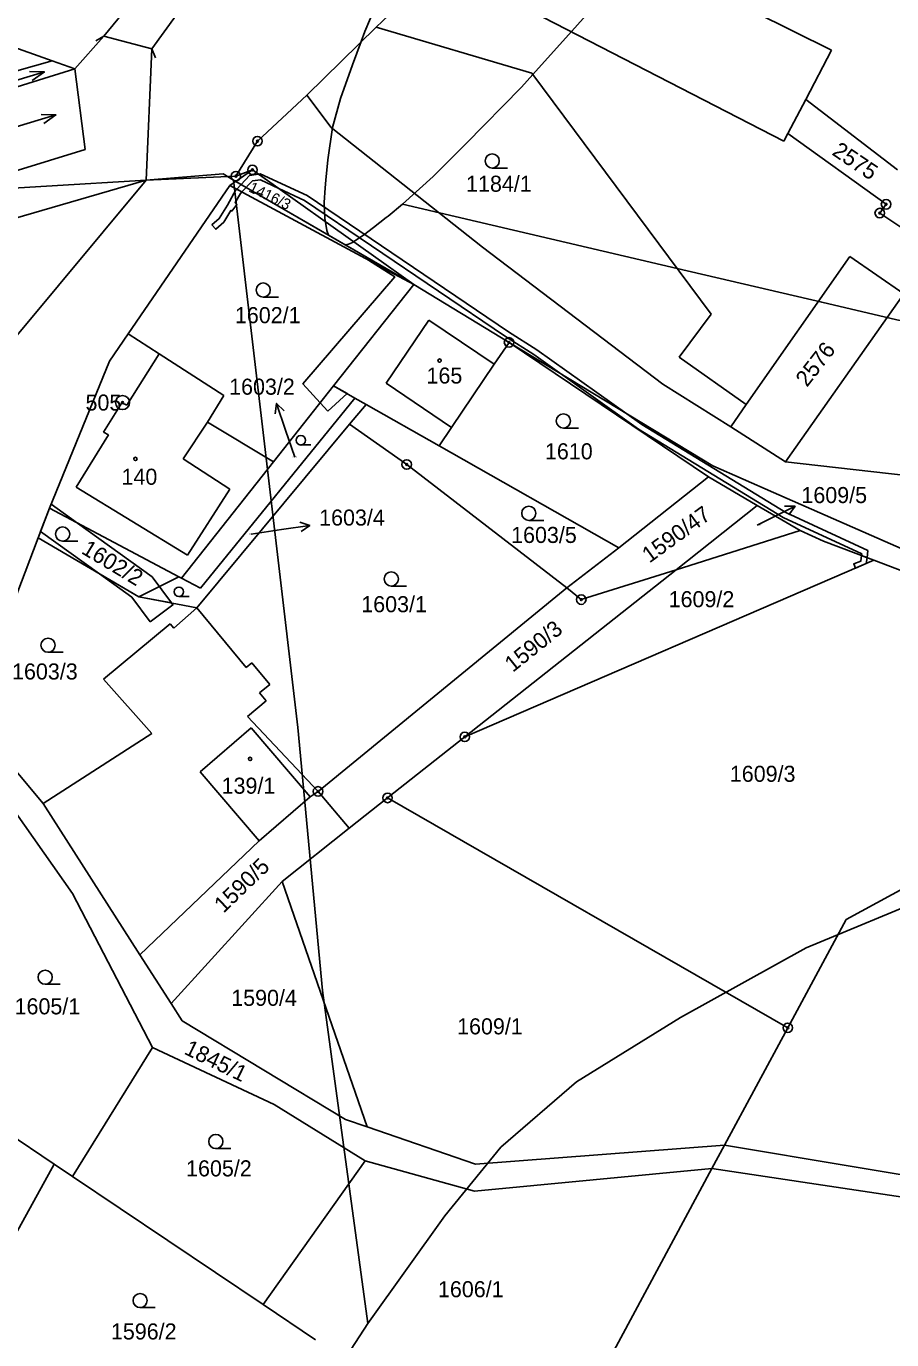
# Model space of a CAD drawing. Extents: x -546762 to -540209, y -1046851 to -1035694.
# Drawn here: x -543445.9 to -543354.2, y -1040714.9 to -1040575.9 of the extents above; entities that cross this region are included whole.
import ezdxf

# ---------------------------------------------------------------- set-up
doc = ezdxf.new("R2010")
doc.units = 0
for name, color, linetype in [('Vrstva 1', 7, 'Continuous'), ('Vrstva 13', 7, 'Continuous'), ('Vrstva 16', 7, 'Continuous'), ('Vrstva 17', 7, 'Continuous'), ('Vrstva 18', 7, 'Continuous'), ('Vrstva 19', 7, 'Continuous'), ('Vrstva 24', 7, 'Continuous'), ('Vrstva 25', 7, 'Continuous'), ('Vrstva 26', 7, 'Continuous'), ('Vrstva 3', 7, 'Continuous'), ('Vrstva 30', 7, 'Continuous'), ('Vrstva 37', 7, 'Continuous'), ('Vrstva 4', 7, 'Continuous'), ('Vrstva 52', 7, 'Continuous'), ('Vrstva 6', 7, 'Continuous')]:
    doc.layers.add(name, color=color, linetype=linetype)

msp = doc.modelspace()

# ---------------------------------------------------------------- linework, layer by layer
at = {"layer": 'Vrstva 1'}
for p, q in [((-543408.83, -1040575.99), (-543416.18, -1040583.21)), ((-543443.15, -1040579.57), (-543463, -1040585.19)), ((-543440.75, -1040580.42), (-543473.23, -1040590.44)), ((-543439.65, -1040588.95), (-543440.75, -1040580.42)), ((-543424.32, -1040592.74), (-543421.93, -1040591.11)), ((-543396.33, -1040611.67), (-543394.76, -1040609.36)), ((-543369.64, -1040615.95), (-543376.76, -1040610.94)), ((-543411.64, -1040618.01), (-543405.6, -1040622.28)), ((-543405.6, -1040622.28), (-543388.63, -1040635.35)), ((-543368.48, -1040626.62), (-543377.08, -1040633.42)), ((-543377.08, -1040633.42), (-543363.94, -1040629.27)), ((-543399.45, -1040651.12), (-543356.13, -1040632.42)), ((-543377.08, -1040633.42), (-543399.45, -1040651.12)), ((-543387.11, -1040636.59), (-543377.08, -1040633.42)), ((-543388.63, -1040635.35), (-543414.99, -1040656.88)), ((-543388.63, -1040635.35), (-543387.11, -1040636.59)), ((-543422.47, -1040648.96), (-543414.99, -1040656.88)), ((-543407.62, -1040657.58), (-543399.45, -1040651.12)), ((-543415.81, -1040657.47), (-543421.21, -1040662.11)), ((-543415.81, -1040657.47), (-543414.99, -1040656.88)), ((-543414.99, -1040656.88), (-543411.68, -1040660.79)), ((-543411.68, -1040660.79), (-543407.62, -1040657.58)), ((-543407.62, -1040657.58), (-543365.25, -1040681.9)), ((-543421.21, -1040662.11), (-543433.85, -1040674.17)), ((-543359.07, -1040670.43), (-543365.25, -1040681.9)), ((-543365.25, -1040681.9), (-543371.93, -1040694.31))]:
    msp.add_line(p, q, dxfattribs=at)
for points in [[(-543432.91, -1040571.12), (-543437.66, -1040576.95)], [(-543432.59, -1040578.31), (-543428.67, -1040572.85)], [(-543408.83, -1040575.99), (-543404.82, -1040572.14)], [(-543368.81, -1040574.39), (-543360.61, -1040578.44)], [(-543437.66, -1040576.95), (-543440.75, -1040580.42)], [(-543408.83, -1040575.99), (-543392.34, -1040580.86)], [(-543443.15, -1040579.57), (-543448.19, -1040577.78)], [(-543433.19, -1040592.18), (-543432.59, -1040578.31)], [(-543440.75, -1040580.42), (-543443.15, -1040579.57)], [(-543360.61, -1040578.44), (-543363.35, -1040583.66)], [(-543392.34, -1040580.86), (-543373.36, -1040606.36)], [(-543416.18, -1040583.21), (-543421.4, -1040588.06)], [(-543413.59, -1040586.61), (-543416.18, -1040583.21)], [(-543363.35, -1040583.66), (-543365.24, -1040587.27)], [(-543353.63, -1040591.1), (-543363.35, -1040583.66)], [(-543413.59, -1040586.61), (-543397.58, -1040599.28)], [(-543421.4, -1040588.06), (-543423.68, -1040591.77)], [(-543365.24, -1040587.27), (-543354.84, -1040594.75)], [(-543454.33, -1040593.48), (-543439.65, -1040588.95)], [(-543459.21, -1040599.73), (-543433.19, -1040592.18)], [(-543447.01, -1040608.82), (-543433.19, -1040592.18)], [(-543424.32, -1040592.74), (-543435.08, -1040608.45)], [(-543404.86, -1040603.25), (-543424.32, -1040592.74)], [(-543354.84, -1040594.75), (-543355.51, -1040595.67)], [(-543355.51, -1040595.67), (-543349.68, -1040599.58)], [(-543397.58, -1040599.28), (-543378.46, -1040613.77)], [(-543358.68, -1040600.27), (-543369.64, -1040615.95)], [(-543358.68, -1040600.27), (-543352.96, -1040604.23)], [(-543413.34, -1040613.96), (-543404.86, -1040603.25)], [(-543365.48, -1040621.99), (-543352.96, -1040604.23)], [(-543376.76, -1040610.94), (-543373.36, -1040606.36)], [(-543435.08, -1040608.45), (-543437.06, -1040611.34)], [(-543435.08, -1040608.45), (-543431.81, -1040610.56)], [(-543443.42, -1040626.92), (-543437.06, -1040611.34)], [(-543431.81, -1040610.56), (-543424.95, -1040614.97)], [(-543400.85, -1040618.37), (-543396.33, -1040611.67)], [(-543419.71, -1040622), (-543413.34, -1040613.96)], [(-543413.34, -1040613.96), (-543411.08, -1040615.25)], [(-543371.29, -1040618.31), (-543378.46, -1040613.77)], [(-543411.08, -1040615.25), (-543427.45, -1040635.37)], [(-543426.69, -1040617.8), (-543424.95, -1040614.97)], [(-543409.9, -1040615.92), (-543411.64, -1040618.01)], [(-543411.08, -1040615.25), (-543409.9, -1040615.92)], [(-543409.9, -1040615.92), (-543402.16, -1040620.31)], [(-543369.64, -1040615.95), (-543371.29, -1040618.31)], [(-543411.64, -1040618.01), (-543427.83, -1040637.44)], [(-543426.69, -1040617.8), (-543419.71, -1040622)], [(-543400.85, -1040618.37), (-543402.16, -1040620.31)], [(-543371.29, -1040618.31), (-543365.48, -1040621.99)], [(-543402.16, -1040620.31), (-543383.13, -1040631.11)], [(-543429.45, -1040634.31), (-543419.71, -1040622)], [(-543352.7, -1040623.46), (-543365.48, -1040621.99)], [(-543383.13, -1040631.11), (-543373.64, -1040623.6)], [(-543443.42, -1040626.92), (-543444.61, -1040630.05)], [(-543443.42, -1040626.92), (-543429.72, -1040634.17)], [(-543444.61, -1040630.05), (-543451.84, -1040648.94)], [(-543444.61, -1040630.05), (-543433.97, -1040636.3)], [(-543383.13, -1040631.11), (-543388.63, -1040635.35)], [(-543433.97, -1040636.3), (-543429.72, -1040634.17)], [(-543429.45, -1040634.31), (-543429.72, -1040634.17)], [(-543427.45, -1040635.37), (-543429.45, -1040634.31)], [(-543433.97, -1040636.3), (-543427.83, -1040637.44)], [(-543430.26, -1040639.61), (-543427.83, -1040637.44)], [(-543427.83, -1040637.44), (-543422.61, -1040643.77)], [(-543437.72, -1040644.99), (-543430.64, -1040639.15)], [(-543430.64, -1040639.15), (-543430.26, -1040639.61)], [(-543422.61, -1040643.77), (-543421.99, -1040643.26)], [(-543421.99, -1040643.26), (-543420.09, -1040645.57)], [(-543432.58, -1040650.76), (-543437.72, -1040644.99)], [(-543420.09, -1040645.57), (-543421.17, -1040646.46)], [(-543421.17, -1040646.46), (-543420.47, -1040647.31)], [(-543420.47, -1040647.31), (-543422.47, -1040648.96)], [(-543451.84, -1040648.94), (-543444.11, -1040658.18)], [(-543444.11, -1040658.18), (-543432.58, -1040650.76)], [(-543448.16, -1040657.49), (-543441, -1040667.68)], [(-543333.92, -1040656.78), (-543359.07, -1040670.43)], [(-543444.11, -1040658.18), (-543433.85, -1040674.17)], [(-543411.68, -1040660.79), (-543418.78, -1040666.41)], [(-543418.78, -1040666.41), (-543430.54, -1040679.33)], [(-543418.78, -1040666.41), (-543409.8, -1040692.4)], [(-543441, -1040667.68), (-543432.53, -1040683.98)], [(-543433.85, -1040674.17), (-543430.54, -1040679.33)], [(-543430.54, -1040679.33), (-543429.36, -1040681.17)], [(-543412.08, -1040691.62), (-543429.36, -1040681.17)], [(-543463.43, -1040682.52), (-543442.94, -1040696.32)], [(-543440.99, -1040697.63), (-543432.53, -1040683.98)], [(-543419.62, -1040690.03), (-543432.53, -1040683.98)], [(-543410.01, -1040695.99), (-543419.62, -1040690.03)], [(-543409.8, -1040692.4), (-543412.08, -1040691.62)], [(-543398.31, -1040696.34), (-543409.8, -1040692.4)], [(-543371.93, -1040694.31), (-543398.31, -1040696.34)], [(-543373.27, -1040696.81), (-543371.93, -1040694.31)], [(-543447.01, -1040703.78), (-543442.94, -1040696.32)], [(-543442.94, -1040696.32), (-543440.99, -1040697.63)], [(-543420.78, -1040711.2), (-543410.01, -1040695.99)], [(-543398.41, -1040699.19), (-543410.01, -1040695.99)], [(-543440.99, -1040697.63), (-543420.78, -1040711.2)], [(-543373.27, -1040696.81), (-543398.41, -1040699.19)], [(-543390.01, -1040727.91), (-543373.27, -1040696.81)], [(-543420.78, -1040711.2), (-543415.25, -1040714.92)]]:
    msp.add_lwpolyline(points, dxfattribs=at)
at = {"layer": 'Vrstva 13'}
msp.add_line((-543433.19, -1040592.18), (-543423.68, -1040591.77), dxfattribs=at)
msp.add_line((-543433.19, -1040592.18), (-543423.68, -1040591.77), dxfattribs=at)
for points in [[(-543454.33, -1040593.48), (-543433.19, -1040592.18)], [(-543454.33, -1040593.48), (-543433.19, -1040592.18)], [(-543421.93, -1040591.11), (-543423.68, -1040591.77)], [(-543421.93, -1040591.11), (-543423.68, -1040591.77)], [(-543404.86, -1040603.25), (-543421.93, -1040591.11)], [(-543404.86, -1040603.25), (-543421.93, -1040591.11)], [(-543394.76, -1040609.36), (-543404.86, -1040603.25)], [(-543394.76, -1040609.36), (-543404.86, -1040603.25)], [(-543394.76, -1040609.36), (-543373.64, -1040623.6)], [(-543394.76, -1040609.36), (-543373.64, -1040623.6)], [(-543368.48, -1040626.62), (-543373.64, -1040623.6)], [(-543368.48, -1040626.62), (-543373.64, -1040623.6)], [(-543368.48, -1040626.62), (-543363.94, -1040629.27)], [(-543368.48, -1040626.62), (-543363.94, -1040629.27)], [(-543361.47, -1040630.39), (-543363.94, -1040629.27)], [(-543361.47, -1040630.39), (-543363.94, -1040629.27)], [(-543356.13, -1040632.42), (-543361.47, -1040630.39)], [(-543356.13, -1040632.42), (-543361.47, -1040630.39)], [(-543333.49, -1040641.01), (-543356.13, -1040632.42)], [(-543333.49, -1040641.01), (-543356.13, -1040632.42)]]:
    msp.add_lwpolyline(points, dxfattribs=at)
at = {"layer": 'Vrstva 16'}
for p, q in [((-543418.42, -1040618.66), (-543419.38, -1040615.82)), ((-543367.15, -1040628.05), (-543364.47, -1040626.71)), ((-543418.84, -1040629.18), (-543415.87, -1040628.75))]:
    msp.add_line(p, q, dxfattribs=at)
for points in [[(-543419.54, -1040616.93), (-543419.38, -1040615.82), (-543418.59, -1040616.61)], [(-543417.45, -1040621.52), (-543418.42, -1040618.66)], [(-543365.58, -1040626.71), (-543364.47, -1040626.71), (-543365.14, -1040627.6)], [(-543416.93, -1040628.4), (-543415.87, -1040628.75), (-543416.79, -1040629.38)], [(-543368.47, -1040628.71), (-543367.15, -1040628.05)], [(-543422.08, -1040629.66), (-543418.84, -1040629.18)]]:
    msp.add_lwpolyline(points, dxfattribs=at)
at = {"layer": 'Vrstva 24'}
for centre, radius in [((-543421.4, -1040588.06), 0.5), ((-543421.4, -1040588.06), 0.1), ((-543421.93, -1040591.11), 0.5), ((-543423.68, -1040591.77), 0.5), ((-543423.68, -1040591.77), 0.1), ((-543421.93, -1040591.11), 0.1), ((-543354.84, -1040594.75), 0.5), ((-543354.84, -1040594.75), 0.1), ((-543355.51, -1040595.67), 0.5), ((-543355.51, -1040595.67), 0.1), ((-543394.76, -1040609.36), 0.5), ((-543394.76, -1040609.36), 0.1), ((-543435.69, -1040615.73), 0.75), ((-543435.69, -1040615.73), 0.1), ((-543405.6, -1040622.28), 0.5), ((-543405.6, -1040622.28), 0.1), ((-543387.11, -1040636.59), 0.5), ((-543387.11, -1040636.59), 0.1), ((-543399.45, -1040651.12), 0.5), ((-543399.45, -1040651.12), 0.1), ((-543414.99, -1040656.88), 0.5), ((-543414.99, -1040656.88), 0.1), ((-543407.62, -1040657.58), 0.5), ((-543407.62, -1040657.58), 0.1), ((-543365.25, -1040681.9), 0.5), ((-543365.25, -1040681.9), 0.1)]:
    msp.add_circle(centre, radius, dxfattribs=at)
at = {"layer": 'Vrstva 25'}
for p, q in [((-543396.54, -1040590.91), (-543394.94, -1040590.91)), ((-543420.79, -1040604.57), (-543419.19, -1040604.57)), ((-543389.01, -1040618.43), (-543387.41, -1040618.43)), ((-543416.81, -1040620.22), (-543415.74, -1040620.22)), ((-543392.67, -1040628.2), (-543391.07, -1040628.2)), ((-543442.03, -1040630.4), (-543440.43, -1040630.4)), ((-543407.23, -1040635.15), (-543405.63, -1040635.15)), ((-543429.72, -1040636.26), (-543428.65, -1040636.26)), ((-543443.58, -1040642.16), (-543441.98, -1040642.16)), ((-543443.88, -1040677.3), (-543442.28, -1040677.3)), ((-543425.81, -1040694.69), (-543424.21, -1040694.69)), ((-543433.83, -1040711.52), (-543432.23, -1040711.52))]:
    msp.add_line(p, q, dxfattribs=at)
for points in [[(-543449.71, -1040582.47), (-543443.97, -1040580.73), (-543445.55, -1040580.69)], [(-543443.97, -1040580.73), (-543445.26, -1040581.64)], [(-543448.48, -1040587.02), (-543442.74, -1040585.28), (-543444.32, -1040585.24)], [(-543442.74, -1040585.28), (-543444.03, -1040586.19)]]:
    msp.add_lwpolyline(points, dxfattribs=at)
for centre, radius in [((-543396.54, -1040590.16), 0.75), ((-543420.79, -1040603.82), 0.75), ((-543402.12, -1040611.29), 0.175), ((-543389.01, -1040617.68), 0.75), ((-543416.81, -1040619.72), 0.503), ((-543434.32, -1040621.7), 0.175), ((-543392.67, -1040627.45), 0.75), ((-543442.03, -1040629.65), 0.75), ((-543407.23, -1040634.4), 0.75), ((-543429.72, -1040635.76), 0.503), ((-543443.58, -1040641.41), 0.75), ((-543422.18, -1040653.44), 0.175), ((-543443.88, -1040676.55), 0.75), ((-543425.81, -1040693.94), 0.75), ((-543433.83, -1040710.77), 0.75)]:
    msp.add_circle(centre, radius, dxfattribs=at)
at = {"layer": 'Vrstva 26'}
for p, q in [((-543437.66, -1040576.95), (-543438.53, -1040577.45)), ((-543432.59, -1040578.31), (-543432.19, -1040579.23))]:
    msp.add_line(p, q, dxfattribs=at)
at = {"layer": 'Vrstva 3'}
for points in [[(-543391.11, -1040574.97), (-543365.67, -1040588.08)], [(-543368.81, -1040574.39), (-543360.61, -1040578.44)], [(-543360.61, -1040578.44), (-543363.35, -1040583.66)], [(-543363.35, -1040583.66), (-543365.24, -1040587.27)], [(-543365.24, -1040587.27), (-543365.67, -1040588.08)], [(-543403.26, -1040607), (-543407.79, -1040613.68)], [(-543396.33, -1040611.67), (-543403.26, -1040607)], [(-543431.81, -1040610.56), (-543435.24, -1040616.02)], [(-543431.81, -1040610.56), (-543424.95, -1040614.97)], [(-543400.85, -1040618.37), (-543396.33, -1040611.67)], [(-543407.79, -1040613.68), (-543400.85, -1040618.37)], [(-543435.78, -1040615.75), (-543437.69, -1040618.85)], [(-543435.24, -1040616.02), (-543435.78, -1040615.75)], [(-543426.69, -1040617.8), (-543424.95, -1040614.97)], [(-543426.69, -1040617.8), (-543429.28, -1040621.7)], [(-543437.18, -1040619.16), (-543440.59, -1040624.69)], [(-543437.69, -1040618.85), (-543437.18, -1040619.16)], [(-543429.28, -1040621.7), (-543424.32, -1040624.89)], [(-543428.8, -1040631.87), (-543440.59, -1040624.69)], [(-543424.32, -1040624.89), (-543428.8, -1040631.87)], [(-543427.48, -1040654.8), (-543422.08, -1040650.16)], [(-543422.08, -1040650.16), (-543415.81, -1040657.47)], [(-543421.21, -1040662.11), (-543427.48, -1040654.8)], [(-543415.81, -1040657.47), (-543421.21, -1040662.11)]]:
    msp.add_lwpolyline(points, dxfattribs=at)
at = {"layer": 'Vrstva 30'}
for p, q in [((-543421.3, -1040591.56), (-543421.1, -1040591.53)), ((-543419.15, -1040593.09), (-543421.3, -1040591.56)), ((-543421.1, -1040591.53), (-543416.13, -1040593.82)), ((-543416.43, -1040594.34), (-543419.15, -1040593.09)), ((-543395.14, -1040608.74), (-543416.43, -1040594.34)), ((-543416.13, -1040593.82), (-543394.82, -1040608.24)), ((-543392.15, -1040610.65), (-543395.14, -1040608.74)), ((-543394.82, -1040608.24), (-543391.81, -1040610.15)), ((-543391.81, -1040610.15), (-543380.7, -1040618.05)), ((-543381.04, -1040618.55), (-543392.15, -1040610.65)), ((-543365.72, -1040627.91), (-543381.04, -1040618.55)), ((-543380.7, -1040618.05), (-543365.44, -1040627.37)), ((-543357.41, -1040631.74), (-543365.72, -1040627.91)), ((-543365.44, -1040627.37), (-543356.75, -1040631.38)), ((-543357.43, -1040631.93), (-543357.41, -1040631.74)), ((-543356.85, -1040632.15), (-543357.43, -1040631.93)), ((-543356.75, -1040631.38), (-543356.85, -1040632.15))]:
    msp.add_line(p, q, dxfattribs=at)
for points in [[(-543421.94, -1040592.27), (-543423.05, -1040593.43), (-543423.6, -1040593.13), (-543422.24, -1040591.71), (-543421.3, -1040591.56), (-543419.15, -1040593.09), (-543421.09, -1040592.14), (-543421.94, -1040592.27)], [(-543423.6, -1040593.13), (-543423.05, -1040593.43), (-543423.21, -1040593.59), (-543423.75, -1040594.57), (-543423.59, -1040594.77), (-543424.12, -1040595.47), (-543424.21, -1040595.4), (-543424.98, -1040596.65), (-543425.82, -1040597.39), (-543426.22, -1040596.93), (-543425.44, -1040596.25), (-543424.58, -1040594.85), (-543423.69, -1040593.23), (-543423.6, -1040593.13)], [(-543413.95, -1040616.64), (-543414.76, -1040615.75), (-543416.59, -1040613.74), (-543406.87, -1040602.44), (-543409.52, -1040600.73), (-543404.86, -1040603.25), (-543413.34, -1040613.96), (-543411.91, -1040614.78), (-543413.95, -1040616.64)], [(-543432.55, -1040634.17), (-543430.5, -1040636.94), (-543433.97, -1040636.3), (-543438.13, -1040633.85), (-543444.36, -1040629.38), (-543443.42, -1040626.92), (-543443.24, -1040626.49), (-543440.47, -1040628.48), (-543432.55, -1040634.17)], [(-543356.85, -1040632.15), (-543356.93, -1040632.77), (-543358.07, -1040633.26), (-543358.25, -1040632.79), (-543357.5, -1040632.5), (-543357.43, -1040631.93), (-543356.85, -1040632.15)], [(-543432.78, -1040638.92), (-543434.69, -1040636.33), (-543438.13, -1040633.85), (-543433.97, -1040636.3), (-543430.5, -1040636.94), (-543430.36, -1040637.14), (-543432.78, -1040638.92)]]:
    msp.add_lwpolyline(points, dxfattribs=at)
at = {"layer": 'Vrstva 37'}
for centre in [(-543402.12, -1040611.29), (-543434.32, -1040621.7), (-543422.18, -1040653.44)]:
    msp.add_circle(centre, 0.175, dxfattribs=at)
at = {"layer": 'Vrstva 4'}
for p, q in [((-543427.48, -1040654.8), (-543422.08, -1040650.16)), ((-543422.08, -1040650.16), (-543415.81, -1040657.47)), ((-543421.21, -1040662.11), (-543427.48, -1040654.8))]:
    msp.add_line(p, q, dxfattribs=at)
for points in [[(-543391.11, -1040574.97), (-543365.67, -1040588.08)], [(-543437.66, -1040576.95), (-543432.59, -1040578.31)], [(-543365.24, -1040587.27), (-543365.67, -1040588.08)], [(-543403.26, -1040607), (-543407.79, -1040613.68)], [(-543396.33, -1040611.67), (-543403.26, -1040607)], [(-543431.81, -1040610.56), (-543435.24, -1040616.02)], [(-543407.79, -1040613.68), (-543400.85, -1040618.37)], [(-543435.78, -1040615.75), (-543437.69, -1040618.85)], [(-543435.24, -1040616.02), (-543435.78, -1040615.75)], [(-543426.69, -1040617.8), (-543429.28, -1040621.7)], [(-543437.18, -1040619.16), (-543440.59, -1040624.69)], [(-543437.69, -1040618.85), (-543437.18, -1040619.16)], [(-543429.28, -1040621.7), (-543424.32, -1040624.89)], [(-543428.8, -1040631.87), (-543440.59, -1040624.69)], [(-543424.32, -1040624.89), (-543428.8, -1040631.87)]]:
    msp.add_lwpolyline(points, dxfattribs=at)
at = {"layer": 'Vrstva 52'}
for points in [[(-543377.75, -1040564.86), (-543392.24, -1040581), (-543393.44, -1040582.34), (-543399.32, -1040588.34), (-543402.79, -1040591.8), (-543406.05, -1040594.73)], [(-543413.96, -1040590.05), (-543413.45, -1040586.63), (-543412.6, -1040583.56), (-543411.32, -1040579.97), (-543410.42, -1040577.52), (-543410.04, -1040576.47), (-543408.24, -1040572.2)], [(-543413.87, -1040598.02), (-543414.06, -1040597.53), (-543414.28, -1040596.22), (-543414.34, -1040594.55), (-543414.23, -1040592.99), (-543414.16, -1040592.21), (-543413.96, -1040590.05)], [(-543496.57, -1040596.65), (-543484.82, -1040595.49), (-543454.33, -1040593.48), (-543433.19, -1040592.18), (-543425.03, -1040591.54), (-543423.93, -1040592.18)], [(-543413.87, -1040598.02), (-543423.93, -1040592.18), (-543425.03, -1040591.54), (-543433.19, -1040592.18), (-543454.33, -1040593.48), (-543478.66, -1040595.08), (-543484.82, -1040595.49), (-543492.41, -1040596.24), (-543496.57, -1040596.65)], [(-543409.7, -1040713.2), (-543414.52, -1040677.95), (-543417.12, -1040650.12), (-543423.93, -1040592.18)], [(-543423.93, -1040592.18), (-543404.86, -1040603.25)], [(-543406.05, -1040594.73), (-543407.57, -1040595.99), (-543407.76, -1040596.15), (-543409.1, -1040597.21), (-543410.16, -1040598), (-543410.97, -1040598.56), (-543411.41, -1040598.84), (-543411.75, -1040598.97)], [(-543091.12, -1040712.41), (-543111.91, -1040700.84), (-543134.91, -1040687.76), (-543164.45, -1040672.33), (-543174.27, -1040667.88), (-543176.28, -1040666.97), (-543193.18, -1040659.82), (-543201.63, -1040656.25), (-543228.82, -1040646.05), (-543266.64, -1040631.83), (-543288.6, -1040624.24), (-543307.42, -1040617.96), (-543322.58, -1040614.04), (-543328.36, -1040612.54), (-543337.74, -1040610.12), (-543337.84, -1040610.1), (-543342.85, -1040609.11), (-543353.68, -1040606.98), (-543361.64, -1040605.12), (-543376.95, -1040601.54), (-543406.05, -1040594.73)], [(-543412.12, -1040599.04), (-543413.87, -1040598.02)], [(-543411.75, -1040598.97), (-543412.12, -1040599.04)], [(-543085.78, -1040738.2), (-543101.67, -1040732.49), (-543140.14, -1040717.52), (-543174.28, -1040705.94), (-543210.23, -1040692.22), (-543217.71, -1040689.38), (-543238.43, -1040681.52), (-543299.21, -1040654.19), (-543333.45, -1040639.76), (-543338.53, -1040637.62), (-543366.74, -1040625.24), (-543373.17, -1040622.42), (-543394.76, -1040609.36), (-543404.86, -1040603.25), (-543412.12, -1040599.04)], [(-543404.86, -1040603.25), (-543394.76, -1040609.36), (-543373.17, -1040622.42), (-543366.74, -1040625.24), (-543338.53, -1040637.62), (-543333.45, -1040639.76), (-543299.21, -1040654.19), (-543238.43, -1040681.52), (-543217.71, -1040689.38), (-543210.23, -1040692.22), (-543174.28, -1040705.94), (-543140.14, -1040717.52), (-543101.67, -1040732.49), (-543085.78, -1040738.2)], [(-543409.7, -1040713.2), (-543401.56, -1040701.79), (-543395.62, -1040694.52), (-543387.63, -1040687.61), (-543376.61, -1040680.82), (-543363.29, -1040673.43), (-543349.84, -1040667.86), (-543340.03, -1040664.59), (-543331.68, -1040663.13), (-543324.29, -1040662.89), (-543317.14, -1040663.62)], [(-543428.35, -1040812.44), (-543430.05, -1040808.57), (-543431.14, -1040803.11), (-543431.62, -1040798.27), (-543431.68, -1040793.9), (-543431.19, -1040784.21), (-543430.34, -1040772.58), (-543428.89, -1040762.4), (-543427.44, -1040751.86), (-543425.5, -1040744.35), (-543422.71, -1040736.35), (-543419.93, -1040730.05), (-543415.08, -1040721.44), (-543409.7, -1040713.2)]]:
    msp.add_lwpolyline(points, dxfattribs=at)
at = {"layer": 'Vrstva 6'}
for points in [[(-543371.93, -1040694.31), (-543317.86, -1040703.34)], [(-543373.27, -1040696.81), (-543317.56, -1040705.14)]]:
    msp.add_lwpolyline(points, dxfattribs=at)

# ---------------------------------------------------------------- texts
at = {"layer": 'Vrstva 16'}
for s, p in [('1603/2', (-543424.4, -1040614.9)), ('1609/5', (-543363.8, -1040626.37)), ('1603/4', (-543414.87, -1040628.75))]:
    msp.add_text(s, height=1.7, dxfattribs=at).set_placement(p)
at = {"layer": 'Vrstva 17'}
msp.add_text('505', height=1.7, dxfattribs=at).set_placement((-543439.61, -1040616.58))
at = {"layer": 'Vrstva 18'}
for s, height, rotation, p in [('2575', 1.7, 326.013, (-543360.66, -1040589.44)), ('1416/3', 1.14, 334.1481, (-543422.42, -1040593.35)), ('2576', 1.7, 52.1285, (-543363.21, -1040614.17)), ('1590/47', 1.7, 36, (-543379.89, -1040632.77)), ('1602/2', 1.7, 328.9964, (-543440.15, -1040631.63)), ('1590/3', 1.7, 38.8278, (-543394.36, -1040644.34)), ('1590/5', 1.7, 43.9623, (-543424.99, -1040669.83)), ('1845/1', 1.7, 333.907, (-543429.28, -1040684.62))]:
    msp.add_text(s, height=height, rotation=rotation, dxfattribs=at).set_placement(p)
for s, height, p in [('1184/1', 1.7, (-543399.31, -1040593.42)), ('1602/1', 1.7, (-543423.79, -1040607.33)), ('1610', 1.7, (-543390.96, -1040621.74)), ('1603/2', 0.1, (-543417.67, -1040621.52)), ('1603/4', 0.1, (-543422.3, -1040629.66)), ('1603/5', 1.7, (-543394.54, -1040630.59)), ('1609/5', 0.1, (-543368.47, -1040628.71)), ('1603/1', 1.7, (-543410.41, -1040637.92)), ('1609/2', 1.7, (-543377.86, -1040637.39)), ('1603/3', 1.7, (-543447.39, -1040645.04)), ('1609/3', 1.7, (-543371.38, -1040655.87)), ('1590/4', 1.7, (-543424.18, -1040679.58)), ('1605/1', 1.7, (-543447.12, -1040680.48)), ('1609/1', 1.7, (-543400.26, -1040682.6)), ('1605/2', 1.7, (-543428.96, -1040697.63)), ('1606/1', 1.7, (-543402.29, -1040710.42)), ('1596/2', 1.7, (-543436.92, -1040714.89))]:
    msp.add_text(s, height=height, dxfattribs=at).set_placement(p)
at = {"layer": 'Vrstva 19'}
for s, p in [('165', (-543403.5, -1040613.72)), ('140', (-543435.8, -1040624.43)), ('139/1', (-543425.2, -1040657.13))]:
    msp.add_text(s, height=1.7, dxfattribs=at).set_placement(p)

doc.saveas('drawing.dxf')
